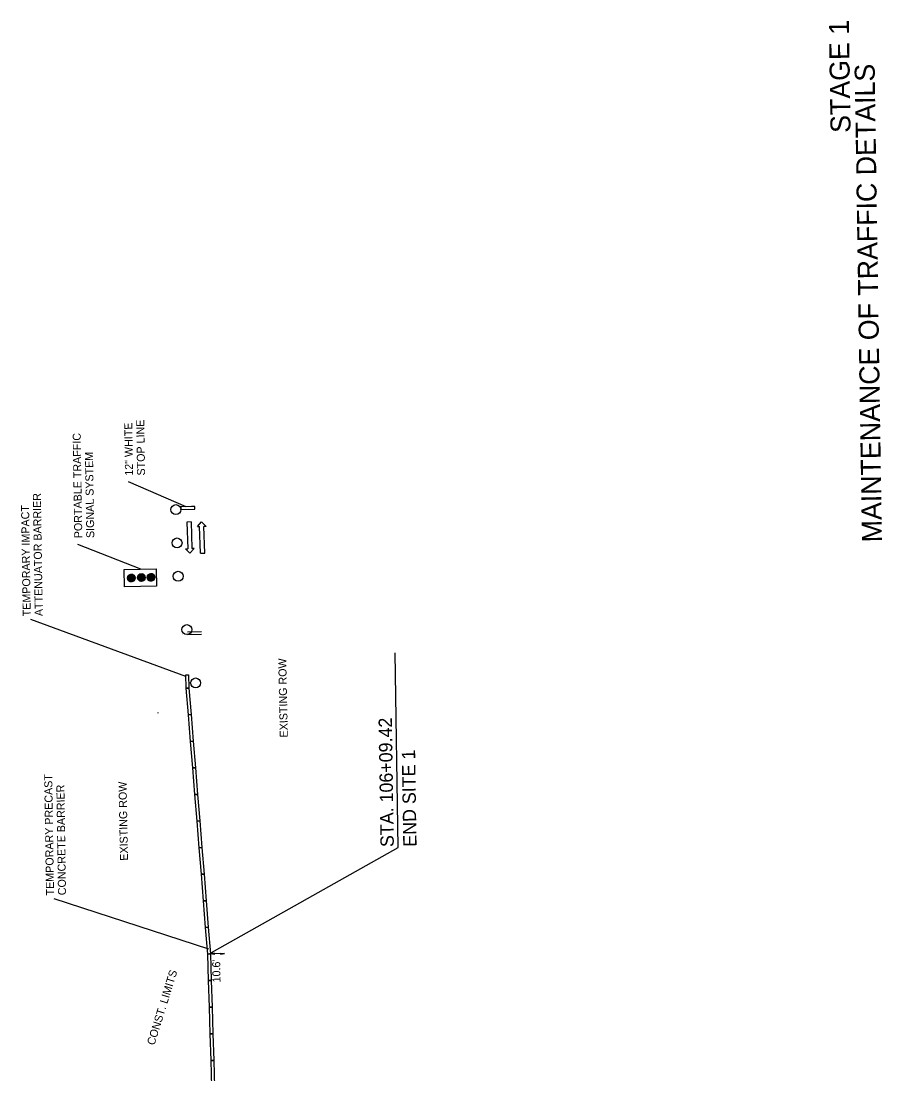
# Model space of a CAD drawing. Extents: x 1770018 to 1773492, y 718230 to 729141.
# Drawn here: x 1770676 to 1771322, y 724857 to 725646 of the extents above; entities that cross this region are included whole.
import ezdxf

# ---------------------------------------------------------------- set-up
doc = ezdxf.new("R2010")
doc.units = 0
for name, color, linetype in [('Default', 7, 'Continuous'), ('E_Existing ROW', 7, 'Continuous'), ('R_Border Notes', 7, 'Continuous'), ('R_Dimension', 7, 'Continuous'), ('R_MOT', 7, 'Continuous'), ('R_Proposed Road', 7, 'Continuous'), ('R_Striping', 7, 'Continuous'), ('T_Vehicle Path Rt', 7, 'Continuous')]:
    doc.layers.add(name, color=color, linetype=linetype)

msp = doc.modelspace()

# ---------------------------------------------------------------- linework, layer by layer
at = {"layer": 'Default'}
for p, q in [((1770760.9, 725226.43), (1770756.77, 725230.43)), ((1770760.98, 725226.52), (1770756.86, 725230.52)), ((1770761.07, 725226.61), (1770756.95, 725230.61)), ((1770761.15, 725226.71), (1770757.04, 725230.69)), ((1770761.22, 725226.81), (1770757.14, 725230.77)), ((1770761.29, 725226.92), (1770757.25, 725230.84)), ((1770761.36, 725227.03), (1770757.35, 725230.91)), ((1770761.42, 725227.14), (1770757.46, 725230.98)), ((1770761.48, 725227.26), (1770757.58, 725231.04)), ((1770761.53, 725227.38), (1770757.7, 725231.1)), ((1770761.58, 725227.51), (1770757.82, 725231.15)), ((1770761.63, 725227.64), (1770757.96, 725231.2)), ((1770761.67, 725227.78), (1770758.09, 725231.24)), ((1770761.7, 725227.92), (1770758.23, 725231.28)), ((1770761.72, 725228.07), (1770758.38, 725231.31)), ((1770761.74, 725228.22), (1770758.54, 725231.33)), ((1770761.75, 725228.39), (1770758.7, 725231.35)), ((1770761.75, 725228.56), (1770758.88, 725231.35)), ((1770761.74, 725228.75), (1770759.06, 725231.34)), ((1770761.71, 725228.95), (1770759.26, 725231.32)), ((1770761.67, 725229.17), (1770759.48, 725231.29)), ((1770761.6, 725229.41), (1770759.73, 725231.22)), ((1770761.48, 725229.7), (1770760.02, 725231.12)), ((1770761.26, 725230.08), (1770760.41, 725230.91)), ((1770767.99, 725226.49), (1770763.94, 725230.41)), ((1770768.09, 725226.56), (1770764.01, 725230.52)), ((1770768.19, 725226.64), (1770764.09, 725230.62)), ((1770768.29, 725226.72), (1770764.17, 725230.72)), ((1770768.38, 725226.81), (1770764.25, 725230.81)), ((1770768.46, 725226.9), (1770764.34, 725230.9)), ((1770768.55, 725226.99), (1770764.43, 725230.99)), ((1770768.63, 725227.09), (1770764.52, 725231.07)), ((1770768.7, 725227.19), (1770764.62, 725231.15)), ((1770768.77, 725227.3), (1770764.73, 725231.22)), ((1770768.84, 725227.41), (1770764.83, 725231.29)), ((1770768.9, 725227.52), (1770764.94, 725231.36)), ((1770768.96, 725227.64), (1770765.06, 725231.42)), ((1770769.01, 725227.76), (1770765.18, 725231.48)), ((1770769.06, 725227.88), (1770765.3, 725231.53)), ((1770769.11, 725228.02), (1770765.44, 725231.58)), ((1770769.15, 725228.15), (1770765.57, 725231.62)), ((1770769.18, 725228.3), (1770765.71, 725231.66)), ((1770769.2, 725228.45), (1770765.86, 725231.69)), ((1770769.22, 725228.6), (1770766.02, 725231.71)), ((1770769.23, 725228.77), (1770766.18, 725231.72)), ((1770769.23, 725228.94), (1770766.36, 725231.73)), ((1770769.22, 725229.13), (1770766.54, 725231.72)), ((1770769.19, 725229.33), (1770766.74, 725231.7)), ((1770769.15, 725229.54), (1770766.96, 725231.67)), ((1770769.08, 725229.79), (1770767.21, 725231.6)), ((1770768.96, 725230.07), (1770767.5, 725231.49)), ((1770768.74, 725230.46), (1770767.89, 725231.29)), ((1770775.2, 725226.56), (1770771.17, 725230.47)), ((1770775.31, 725226.63), (1770771.24, 725230.57)), ((1770775.41, 725226.71), (1770771.32, 725230.68)), ((1770775.5, 725226.79), (1770771.39, 725230.78)), ((1770775.6, 725226.87), (1770771.47, 725230.87)), ((1770775.69, 725226.96), (1770771.56, 725230.96)), ((1770775.77, 725227.05), (1770771.65, 725231.05)), ((1770775.85, 725227.15), (1770771.74, 725231.14)), ((1770775.93, 725227.25), (1770771.84, 725231.22)), ((1770776, 725227.35), (1770771.94, 725231.29)), ((1770776.07, 725227.46), (1770772.04, 725231.36)), ((1770776.14, 725227.57), (1770772.15, 725231.43)), ((1770776.2, 725227.68), (1770772.26, 725231.5)), ((1770776.25, 725227.8), (1770772.38, 725231.56)), ((1770776.35, 725228.05), (1770772.63, 725231.66)), ((1770776.39, 725228.19), (1770772.76, 725231.71)), ((1770776.43, 725228.33), (1770772.9, 725231.75)), ((1770776.46, 725228.47), (1770773.05, 725231.78)), ((1770776.48, 725228.63), (1770773.2, 725231.81)), ((1770776.5, 725228.79), (1770773.36, 725231.83)), ((1770776.5, 725228.96), (1770773.53, 725231.84)), ((1770776.5, 725229.13), (1770773.71, 725231.84)), ((1770776.48, 725229.33), (1770773.9, 725231.83)), ((1770776.45, 725229.53), (1770774.11, 725231.8)), ((1770776.39, 725229.76), (1770774.33, 725231.75)), ((1770776.3, 725230.02), (1770774.6, 725231.67)), ((1770776.15, 725230.34), (1770774.92, 725231.53)), ((1770759.05, 725225.61), (1770756, 725228.56)), ((1770758.88, 725225.6), (1770756, 725228.39)), ((1770759.22, 725225.62), (1770756.01, 725228.73)), ((1770758.69, 725225.61), (1770756.02, 725228.2)), ((1770759.37, 725225.64), (1770756.03, 725228.89)), ((1770758.49, 725225.63), (1770756.04, 725228.01)), ((1770759.52, 725225.67), (1770756.06, 725229.03)), ((1770759.66, 725225.71), (1770756.09, 725229.18)), ((1770758.28, 725225.66), (1770756.09, 725227.79)), ((1770759.8, 725225.75), (1770756.13, 725229.31)), ((1770758.03, 725225.73), (1770756.16, 725227.54)), ((1770759.93, 725225.8), (1770756.17, 725229.45)), ((1770760.06, 725225.85), (1770756.22, 725229.57)), ((1770760.18, 725225.91), (1770756.27, 725229.7)), ((1770757.74, 725225.84), (1770756.27, 725227.26)), ((1770760.29, 725225.97), (1770756.33, 725229.81)), ((1770760.4, 725226.04), (1770756.39, 725229.93)), ((1770760.51, 725226.11), (1770756.46, 725230.04)), ((1770757.35, 725226.04), (1770756.49, 725226.87)), ((1770760.61, 725226.18), (1770756.53, 725230.14)), ((1770760.71, 725226.26), (1770756.61, 725230.24)), ((1770760.81, 725226.34), (1770756.69, 725230.34)), ((1770766.53, 725225.98), (1770763.48, 725228.94)), ((1770766.36, 725225.98), (1770763.48, 725228.77)), ((1770766.7, 725226), (1770763.49, 725229.11)), ((1770766.17, 725225.99), (1770763.5, 725228.58)), ((1770766.85, 725226.02), (1770763.51, 725229.26)), ((1770765.97, 725226.01), (1770763.52, 725228.38)), ((1770767, 725226.05), (1770763.54, 725229.41)), ((1770767.14, 725226.09), (1770763.57, 725229.56)), ((1770765.76, 725226.04), (1770763.57, 725228.17)), ((1770767.28, 725226.13), (1770763.61, 725229.69)), ((1770765.51, 725226.11), (1770763.64, 725227.92)), ((1770767.41, 725226.18), (1770763.65, 725229.82)), ((1770767.54, 725226.23), (1770763.7, 725229.95)), ((1770767.66, 725226.29), (1770763.75, 725230.07)), ((1770765.22, 725226.21), (1770763.75, 725227.64)), ((1770767.77, 725226.35), (1770763.81, 725230.19)), ((1770767.88, 725226.42), (1770763.88, 725230.3)), ((1770764.83, 725226.42), (1770763.97, 725227.25)), ((1770773.71, 725226.09), (1770770.75, 725228.96)), ((1770773.88, 725226.1), (1770770.76, 725229.13)), ((1770773.53, 725226.09), (1770770.76, 725228.78)), ((1770774.04, 725226.12), (1770770.77, 725229.29)), ((1770773.33, 725226.11), (1770770.78, 725228.59)), ((1770774.19, 725226.15), (1770770.79, 725229.44)), ((1770773.12, 725226.14), (1770770.81, 725228.38)), ((1770774.34, 725226.18), (1770770.82, 725229.59)), ((1770774.47, 725226.22), (1770770.85, 725229.73)), ((1770772.89, 725226.19), (1770770.87, 725228.15)), ((1770774.61, 725226.26), (1770770.9, 725229.86)), ((1770774.74, 725226.31), (1770770.94, 725229.99)), ((1770772.63, 725226.27), (1770770.96, 725227.88)), ((1770774.86, 725226.37), (1770770.99, 725230.12)), ((1770774.98, 725226.43), (1770771.05, 725230.24)), ((1770775.09, 725226.49), (1770771.11, 725230.35)), ((1770772.29, 725226.42), (1770771.12, 725227.56)), ((1770797.34, 725186.19), (1770797.5, 725186.19)), ((1770958.76, 725026.38), (1770956.51, 725172.33)), ((1770779.07, 725127.21), (1770778.8, 725127.48)), ((1770817.16, 724946.59), (1770958.76, 725026.38))]:
    msp.add_line(p, q, dxfattribs=at)
msp.add_lwpolyline([(1770753.75, 725221.97), (1770753.55, 725234.96), (1770777.52, 725235.33), (1770777.72, 725222.34)], close=True, dxfattribs=at)
for centre in [(1770758.88, 725228.48), (1770766.36, 725228.85), (1770773.63, 725228.97)]:
    msp.add_circle(centre, 2.87, dxfattribs=at)
at = {"layer": 'R_Border Notes'}
for p, q in [((1770803.62, 725270.55), (1770800.43, 725270.45)), ((1770800.43, 725270.45), (1770801.06, 725250.47)), ((1770803.62, 725270.55), (1770804.26, 725250.58)), ((1770808.43, 725267.03), (1770811.52, 725270.64)), ((1770811.52, 725270.64), (1770814.83, 725267.23)), ((1770808.43, 725267.03), (1770810.03, 725267.08)), ((1770810.67, 725247.1), (1770810.03, 725267.08)), ((1770814.83, 725267.23), (1770813.23, 725267.18)), ((1770813.87, 725247.21), (1770813.23, 725267.18)), ((1770799.47, 725250.42), (1770801.06, 725250.47)), ((1770802.78, 725247.02), (1770799.47, 725250.42)), ((1770805.86, 725250.63), (1770802.78, 725247.02)), ((1770805.86, 725250.63), (1770804.26, 725250.58)), ((1770810.67, 725247.1), (1770813.87, 725247.21))]:
    msp.add_line(p, q, dxfattribs=at)
at = {"layer": 'R_Dimension'}
for p, q in [((1770799.9, 725281.96), (1770756.69, 725300.59)), ((1770765.85, 725235.15), (1770718.63, 725253.72)), ((1770799.57, 725154.68), (1770683.53, 725197.29))]:
    msp.add_line(p, q, dxfattribs=at)
msp.add_lwpolyline([(1770817.04, 724950.31), (1770700.98, 724988.02)], dxfattribs=at)
at = {"layer": 'R_MOT'}
for centre in [(1770792.22, 725279.74), (1770793.07, 725254.76), (1770793.91, 725229.77), (1770800.47, 725189.78), (1770807.03, 725149.79)]:
    msp.add_circle(centre, 3.75, dxfattribs=at)
at = {"layer": 'R_Proposed Road'}
for p, q in [((1770821.14, 724947.16), (1770818.15, 724946.66)), ((1770821.16, 724946.26), (1770818.15, 724946.66)), ((1770821.14, 724947.09), (1770818.65, 724946.67)), ((1770821.15, 724946.34), (1770818.65, 724946.67)), ((1770821.14, 724947.01), (1770819.17, 724946.68)), ((1770821.15, 724946.42), (1770819.17, 724946.68)), ((1770821.14, 724946.94), (1770819.67, 724946.69)), ((1770821.15, 724946.49), (1770819.67, 724946.69)), ((1770821.15, 724946.86), (1770820.17, 724946.7)), ((1770821.15, 724946.57), (1770820.17, 724946.7)), ((1770821.15, 724946.79), (1770820.67, 724946.71)), ((1770821.15, 724946.64), (1770820.67, 724946.71)), ((1770821.16, 724946.26), (1770821.14, 724947.16)), ((1770825.75, 724947.25), (1770828.76, 724946.85)), ((1770825.75, 724947.25), (1770825.77, 724946.35)), ((1770825.75, 724947.17), (1770828.26, 724946.84)), ((1770825.75, 724947.1), (1770827.74, 724946.83)), ((1770825.75, 724947.02), (1770827.24, 724946.82)), ((1770825.76, 724946.94), (1770826.73, 724946.82)), ((1770825.76, 724946.87), (1770826.23, 724946.81)), ((1770825.76, 724946.42), (1770828.26, 724946.84)), ((1770825.76, 724946.5), (1770827.74, 724946.83)), ((1770825.76, 724946.65), (1770826.73, 724946.82)), ((1770825.76, 724946.58), (1770827.24, 724946.82)), ((1770825.76, 724946.73), (1770826.23, 724946.81)), ((1770825.77, 724946.35), (1770828.76, 724946.85))]:
    msp.add_line(p, q, dxfattribs=at)
at = {"layer": 'R_Striping'}
for p, q in [((1770795.89, 725281.89), (1770795.95, 725280.17)), ((1770795.95, 725280.17), (1770795.95, 725280.16)), ((1770795.97, 725279.9), (1770806.48, 725280.06)), ((1770806.48, 725280.06), (1770806.44, 725282.06)), ((1770800.95, 725188.25), (1770811.3, 725188.41)), ((1770800.97, 725186.25), (1770811.34, 725186.41)), ((1770828.7, 724946.85), (1770818.15, 724946.66))]:
    msp.add_line(p, q, dxfattribs=at)
msp.add_lwpolyline([(1770806.44, 725282.06), (1770803.91, 725282.02), (1770795.89, 725281.89)], dxfattribs=at)
for start, end in [(2.93525, 6.53038), (2.55633, 2.74579), (2.55633, 2.74579)]:
    msp.add_arc((1770792.22, 725279.74), 3.75, start, end, dxfattribs=at)
at = {"layer": 'T_Vehicle Path Rt'}
for points in [[(1770800.02, 725145.96), (1770799.74, 725155.95), (1770801.74, 725156.01), (1770802.02, 725146.01)], [(1770801.64, 725125.92), (1770800.03, 725145.85), (1770802.02, 725146.01), (1770803.63, 725126.08)], [(1770803.25, 725105.98), (1770801.64, 725125.92), (1770803.63, 725126.08), (1770805.24, 725106.14)], [(1770804.86, 725086.05), (1770803.25, 725105.98), (1770805.24, 725106.14), (1770806.86, 725086.21)], [(1770806.48, 725066.11), (1770804.86, 725086.05), (1770806.86, 725086.21), (1770808.47, 725066.27)], [(1770808.09, 725046.18), (1770806.48, 725066.11), (1770808.47, 725066.27), (1770810.08, 725046.34)], [(1770809.7, 725026.24), (1770808.09, 725046.18), (1770810.08, 725046.34), (1770811.7, 725026.4)], [(1770811.32, 725006.31), (1770809.7, 725026.24), (1770811.7, 725026.4), (1770813.31, 725006.47)], [(1770812.93, 724986.37), (1770811.32, 725006.31), (1770813.31, 725006.47), (1770814.92, 724986.53)], [(1770814.54, 724966.44), (1770812.93, 724986.37), (1770814.92, 724986.53), (1770816.54, 724966.6)], [(1770816.16, 724946.5), (1770814.54, 724966.44), (1770816.54, 724966.6), (1770818.15, 724946.66)], [(1770816.74, 724926.58), (1770816.13, 724946.57), (1770818.13, 724946.63), (1770818.74, 724926.64)], [(1770817.35, 724906.59), (1770816.74, 724926.58), (1770818.74, 724926.64), (1770819.35, 724906.65)], [(1770817.95, 724886.6), (1770817.35, 724906.59), (1770819.35, 724906.65), (1770819.95, 724886.66)], [(1770818.56, 724866.61), (1770817.95, 724886.6), (1770819.95, 724886.66), (1770820.56, 724866.67)], [(1770819.17, 724846.62), (1770818.56, 724866.61), (1770820.56, 724866.67), (1770821.17, 724846.68)]]:
    msp.add_lwpolyline(points, close=True, dxfattribs=at)

# ---------------------------------------------------------------- texts
at = {"layer": 'Default'}
for s, height, p in [('STAGE 1', 15, (1771298.02, 725562.35)), ('MAINTENANCE OF TRAFFIC DETAILS', 15, (1771321.54, 725255.35)), ('STA. 106+09.42', 10, (1770955.63, 725026.83)), ('END SITE 1', 10, (1770972.67, 725027.09))]:
    msp.add_text(s, height=height, rotation=90.88269, dxfattribs=at).set_placement(p)
at = {"layer": 'E_Existing ROW'}
for p in [(1770876.16, 725109), (1770756.38, 725016.59)]:
    msp.add_text('EXISTING ROW', height=6, rotation=91.16794, dxfattribs=at).set_placement(p)
at = {"layer": 'R_Dimension'}
for s, rotation, p in [('12" WHITE', 90.88269, (1770760.12, 725305.24)), ('STOP LINE', 90.88269, (1770769.12, 725305.38)), ('PORTABLE TRAFFIC', 90.88269, (1770722.06, 725258.37)), ('SIGNAL SYSTEM', 90.88269, (1770731.06, 725258.51)), ('ATTENUATOR BARRIER', 90.88269, (1770692.44, 725199.96)), ('TEMPORARY IMPACT', 90.88269, (1770683.44, 725199.82)), ('TEMPORARY PRECAST', 90.88269, (1770700.89, 724990.55)), ('CONCRETE BARRIER', 90.88269, (1770709.89, 724990.69)), ("10.6'", 90.88269, (1770825.69, 724925.3)), ('CONST. LIMITS', 72.76832, (1770776.08, 724877.75))]:
    msp.add_text(s, height=6, rotation=rotation, dxfattribs=at).set_placement(p)

doc.saveas('drawing.dxf')
